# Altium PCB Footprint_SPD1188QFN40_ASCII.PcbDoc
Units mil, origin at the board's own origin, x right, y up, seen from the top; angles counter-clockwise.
Board outline 6000 x 4000 mil, 2 copper layers (Top Layer, Bottom Layer); 1 components, 0 nets, 41 pads, 0 vias.
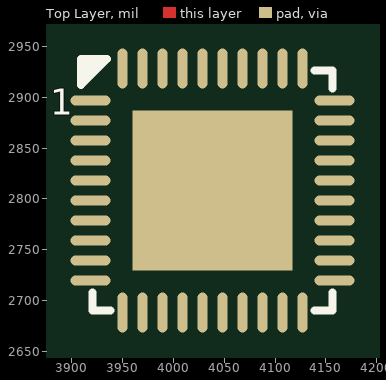
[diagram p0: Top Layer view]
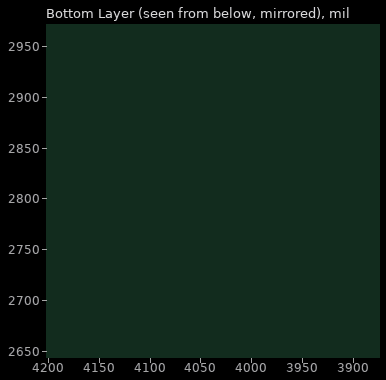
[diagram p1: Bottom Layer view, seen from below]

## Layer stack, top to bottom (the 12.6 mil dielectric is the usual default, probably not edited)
Top Solder: solder mask 0.4, Solder Resist, Dk 3.5
Top Layer: signal copper 1.4
Dielectric 1: dielectric 12.6, FR-4, Dk 4.8
Bottom Layer: signal copper 1.4
Bottom Solder: solder mask 0.4, Solder Resist, Dk 3.5

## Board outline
1000,1000 7000,1000 7000,5000 1000,5000

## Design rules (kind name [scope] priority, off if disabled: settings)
AssemblyTestPointUsage [All] p0: scope1count=1 scope1_0_kind=Board scope1_0_value=Board scope2count=1 scope2_0_kind=Board scope2_0_value=Board commentlength=0
AssemblyTestpoint [All] p0: scope1count=1 scope1_0_kind=Board scope1_0_value=Board scope2count=1 scope2_0_kind=Board scope2_0_value=Board commentlength=0
Clearance [All] p0: scope1count=1 scope1_0_kind=Board scope1_0_value=Board scope2count=1 scope2_0_kind=Board scope2_0_value=Board commentlength=0 gap=10
Clearance [All] p1: gap=10 ignorepadtopadclearanceinfootprint=FALSE except(0: Arc-Hole Track-Hole SMDPad-Hole THPad-Hole Via-Hole Fill-Hole Poly-Hole Region-Hole Text-Hole)
ComponentClearance [All] p0: scope1count=1 scope1_0_kind=Board scope1_0_value=Board scope2count=1 scope2_0_kind=Board scope2_0_value=Board commentlength=0 gap=10 collisioncheckmode=3
DiffPairsRouting [All] p0: scope1count=1 scope1_0_kind=Board scope1_0_value=Board scope2count=1 scope2_0_kind=Board scope2_0_value=Board commentlength=0
FabricationTestPointUsage [All] p0: scope1count=1 scope1_0_kind=Board scope1_0_value=Board scope2count=1 scope2_0_kind=Board scope2_0_value=Board commentlength=0 valid=0 allowmultiple=FALSE
FabricationTestpoint [All] p0: scope1count=1 scope1_0_kind=Board scope1_0_value=Board scope2count=1 scope2_0_kind=Board scope2_0_value=Board commentlength=0 side=3 testpointundercomponent=TRUE minsize=40 maxsize=100 preferedsize=60 minholesize=0 maxholesize=40 preferedholesize=32 testpointgrid=1
FanoutControl Fanout_BGA [All] p0 off: scope1count=1 scope1_0_kind=Board scope1_0_value=Board scope2count=1 scope2_0_kind=Board scope2_0_value=Board commentlength=69 // Protel DXP Scope 1 Expression Was: IsBGA   Fanout_BGA (Default Rule)
FanoutControl Fanout_LCC [All] p0 off: scope1count=1 scope1_0_kind=Board scope1_0_value=Board scope2count=1 scope2_0_kind=Board scope2_0_value=Board commentlength=69 // Protel DXP Scope 1 Expression Was: IsLCC   Fanout_LCC (Default Rule)
FanoutControl Fanout_SOIC [All] p0 off: scope1count=1 scope1_0_kind=Board scope1_0_value=Board scope2count=1 scope2_0_kind=Board scope2_0_value=Board commentlength=71 // Protel DXP Scope 1 Expression Was: IsSOIC   Fanout_SOIC (Default Rule)
FanoutControl Fanout_Small [All] p0 off: scope1count=1 scope1_0_kind=Board scope1_0_value=Board scope2count=1 scope2_0_kind=Board scope2_0_value=Board commentlength=84 // Protel DXP Scope 1 Expression Was: (CompPinCount < 5)   Fanout_Small (Default Rule)
FanoutControl Fanout_Default [All] p0: scope1count=1 scope1_0_kind=Board scope1_0_value=Board scope2count=1 scope2_0_kind=Board scope2_0_value=Board commentlength=30 // Fanout_Default (Default Rule)
Height [All] p0: scope1count=1 scope1_0_kind=Board scope1_0_value=Board scope2count=1 scope2_0_kind=Board scope2_0_value=Board commentlength=0
HoleSize [All] p0: scope1count=1 scope1_0_kind=Board scope1_0_value=Board scope2count=1 scope2_0_kind=Board scope2_0_value=Board commentlength=0 absolutevalues=TRUE maxlimit=100 minlimit=1 maxpercent=80.000 minpercent=20.000
HoleToHoleClearance [All] p0: scope1count=1 scope1_0_kind=Board scope1_0_value=Board scope2count=1 scope2_0_kind=Board scope2_0_value=Board commentlength=0
LayerPairs [All] p0: scope1count=1 scope1_0_kind=Board scope1_0_value=Board scope2count=1 scope2_0_kind=Board scope2_0_value=Board commentlength=0 enforce=TRUE
MinimumSolderMaskSliver [All] p0: scope1count=1 scope1_0_kind=Board scope1_0_value=Board scope2count=1 scope2_0_kind=Board scope2_0_value=Board commentlength=0
NetAntennae [All] p0: scope1count=1 scope1_0_kind=Board scope1_0_value=Board scope2count=1 scope2_0_kind=Board scope2_0_value=Board commentlength=0
PasteMaskExpansion [All] p0: scope1count=1 scope1_0_kind=Board scope1_0_value=Board scope2count=1 scope2_0_kind=Board scope2_0_value=Board commentlength=0 expansion=0
PlaneClearance [All] p0: scope1count=1 scope1_0_kind=Board scope1_0_value=Board scope2count=1 scope2_0_kind=Board scope2_0_value=Board commentlength=0 clearance=20
PlaneConnect [All] p0: scope1count=1 scope1_0_kind=Board scope1_0_value=Board scope2count=1 scope2_0_kind=Board scope2_0_value=Board commentlength=0 planeconnectstyle=Relief reliefexpansion=20 reliefentries=4 reliefconductorwidth=10 reliefairgap=10
PolygonConnect [All] p0: scope1count=1 scope1_0_kind=Board scope1_0_value=Board scope2count=1 scope2_0_kind=Board scope2_0_value=Board commentlength=0 connectstyle=Relief reliefconductorwidth=10 reliefentries=4 polygonreliefangle="90 Angle"
PolygonConnect [All] p1: connectstyle=Relief reliefconductorwidth=10 reliefentries=4 polygonreliefangle="90 Angle" airgapwidth=10
RoutingCorners [All] p0: scope1count=1 scope1_0_kind=Board scope1_0_value=Board scope2count=1 scope2_0_kind=Board scope2_0_value=Board commentlength=0 cornerstyle=45-Degree minsetback=100 maxsetback=100
RoutingLayers [All] p0: scope1count=1 scope1_0_kind=Board scope1_0_value=Board scope2count=1 scope2_0_kind=Board scope2_0_value=Board commentlength=0 top layer=Automatic bottom layer=Automatic
RoutingPriority [All] p0: scope1count=1 scope1_0_kind=Board scope1_0_value=Board scope2count=1 scope2_0_kind=Board scope2_0_value=Board commentlength=0
RoutingTopology [All] p0: scope1count=1 scope1_0_kind=Board scope1_0_value=Board scope2count=1 scope2_0_kind=Board scope2_0_value=Board commentlength=0 topology=Shortest
RoutingVias [All] p0: scope1count=1 scope1_0_kind=Board scope1_0_value=Board scope2count=1 scope2_0_kind=Board scope2_0_value=Board commentlength=0 holewidth=28 width=50 viastyle="Through Hole" minholewidth=28 minwidth=50 maxholewidth=28 maxwidth=50
RoutingVias [All] p1: holewidth=28 width=50 viastyle="Through Hole" minholewidth=28 minwidth=50 maxholewidth=28 maxwidth=50
ShortCircuit [All] p0: scope1count=1 scope1_0_kind=Board scope1_0_value=Board scope2count=1 scope2_0_kind=Board scope2_0_value=Board commentlength=0 allowed=FALSE
SilkToBoardRegionClearance [All] p0: scope1count=1 scope1_0_kind=Board scope1_0_value=Board scope2count=1 scope2_0_kind=Board scope2_0_value=Board commentlength=0
SilkToSilkClearance [All] p0: scope1count=1 scope1_0_kind=Board scope1_0_value=Board scope2count=1 scope2_0_kind=Board scope2_0_value=Board commentlength=0
SilkToSolderMaskClearance [All] p0 off: scope1count=1 scope1_0_kind=Board scope1_0_value=Board scope2count=1 scope2_0_kind=Board scope2_0_value=Board commentlength=44 // Protel DXP Scope 1 Expression Was: IsPad
SolderMaskExpansion [All] p0: scope1count=1 scope1_0_kind=Board scope1_0_value=Board scope2count=1 scope2_0_kind=Board scope2_0_value=Board commentlength=0 expansion=4
SolderMaskExpansion [All] p1: expansion=4 istentingtop=FALSE
UnRoutedNet [All] p0: scope1count=1 scope1_0_kind=Board scope1_0_value=Board scope2count=1 scope2_0_kind=Board scope2_0_value=Board commentlength=0
UnpouredPolygon [All] p0: scope1count=1 scope1_0_kind=Board scope1_0_value=Board scope2count=1 scope2_0_kind=Board scope2_0_value=Board commentlength=0
Width [All] p0: scope1count=1 scope1_0_kind=Board scope1_0_value=Board scope2count=1 scope2_0_kind=Board scope2_0_value=Board commentlength=0 maxlimit=10 minlimit=10 preferedwidth=10
Width [All] p1: maxlimit=10 minlimit=10 preferedwidth=10
30 further rules are at their usual default settings.

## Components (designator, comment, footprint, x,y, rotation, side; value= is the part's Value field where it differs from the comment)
? "" QFN-40-0.5 3705,2805 r0 top

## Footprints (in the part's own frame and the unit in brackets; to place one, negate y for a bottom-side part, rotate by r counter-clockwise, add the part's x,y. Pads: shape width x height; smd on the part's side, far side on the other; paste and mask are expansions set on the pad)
QFN-40-0.5 [mm]
  rect 4x4 smd: 0(8.47,0.081)
  oval 1x0.25 smd: 1(5.42,2.331) 2(5.42,1.832) 3(5.42,1.332) 4(5.42,0.832) 5(5.42,0.332) 6(5.42,-0.169) 7(5.42,-0.669) 8(5.42,-1.169) 9(5.42,-1.669) 10(5.42,-2.169) 21(11.52,-2.169) 22(11.52,-1.669) 23(11.52,-1.169) 24(11.52,-0.669) 25(11.52,-0.169) 26(11.52,0.332) 27(11.52,0.832) 28(11.52,1.332) 29(11.52,1.832) 30(11.52,2.331)
  oval 0.25x1 smd: 11(6.22,-2.969) 12(6.72,-2.969) 13(7.22,-2.969) 14(7.72,-2.969) 15(8.22,-2.969) 16(8.72,-2.969) 17(9.22,-2.969) 18(9.72,-2.969) 19(10.22,-2.969) 20(10.72,-2.969) 31(10.72,3.131) 32(10.22,3.131) 33(9.72,3.131) 34(9.22,3.131) 35(8.72,3.131) 36(8.22,3.131) 37(7.72,3.131) 38(7.22,3.131) 39(6.72,3.131) 40(6.22,3.131)
  silkscreen extent 5.18,-2.92 11.47,3.38

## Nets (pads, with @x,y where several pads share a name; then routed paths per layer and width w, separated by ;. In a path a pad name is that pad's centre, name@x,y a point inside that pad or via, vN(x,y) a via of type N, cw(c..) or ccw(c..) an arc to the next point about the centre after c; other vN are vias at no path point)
pads on no net: ?.0 ?.1 ?.2 ?.3 ?.4 ?.5 ?.6 ?.7 ?.8 ?.9 ?.10 ?.11 ?.12 ?.13 ?.14 ?.15 ?.16 ?.17 ?.18 ?.19 ?.20 ?.21 ?.22 ?.23 ?.24 ?.25 ?.26 ?.27 ?.28 ?.29 ?.30 ?.31 ?.32 ?.33 ?.34 ?.35 ?.36 ?.37 ?.38 ?.39 ?.40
